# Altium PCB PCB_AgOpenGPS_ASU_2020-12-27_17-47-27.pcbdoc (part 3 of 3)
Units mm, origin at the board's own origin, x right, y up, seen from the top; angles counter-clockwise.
Board outline 200.19 x 135.91 mm, 2 copper layers (Top Layer, Bottom Layer); 260 components, 183 nets, 970 pads, 382 vias.
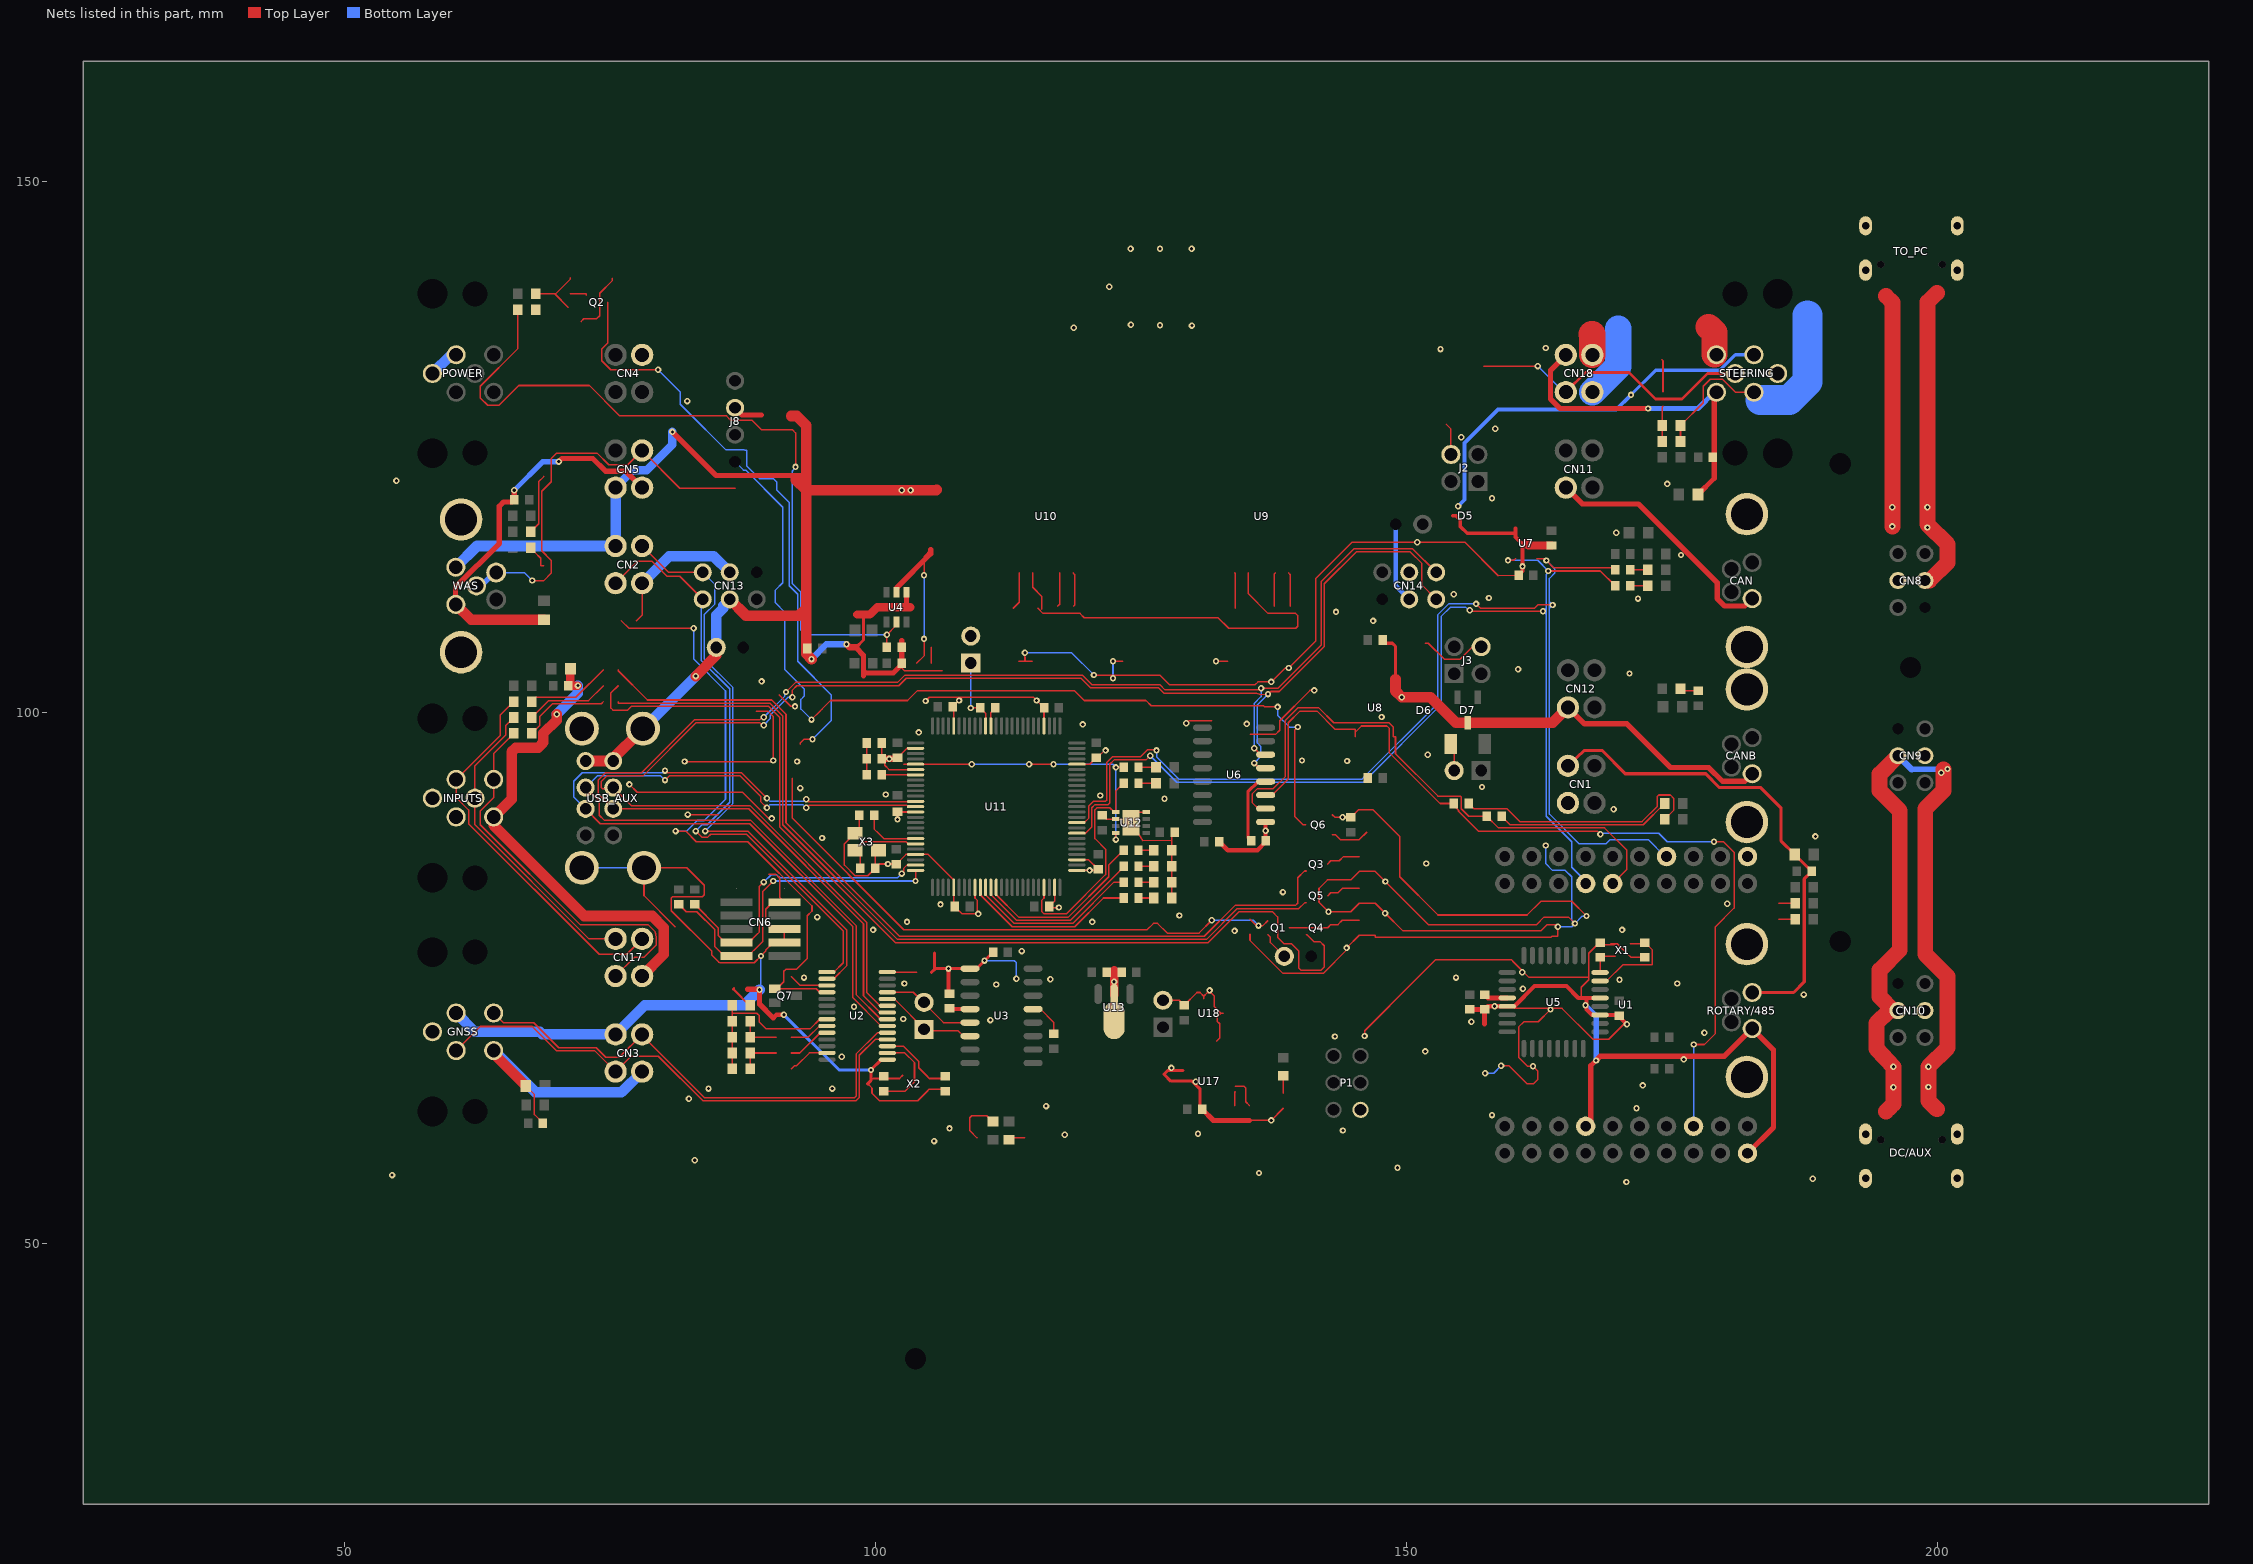
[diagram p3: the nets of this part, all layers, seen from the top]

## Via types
v1: diameter 0.6, hole 0.3, Top Layer to Bottom Layer, 381 vias
v2: diameter 0.61, hole 0.305, Top Layer to Bottom Layer, 1 vias

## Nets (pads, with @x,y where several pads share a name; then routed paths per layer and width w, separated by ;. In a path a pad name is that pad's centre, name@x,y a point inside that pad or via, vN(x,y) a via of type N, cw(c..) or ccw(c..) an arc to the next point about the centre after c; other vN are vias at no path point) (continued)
GND: 12V.1 BOOT.2 C1.1 C2.2 C3.2 C4.2 C5.1 C6.1 C8.1 C9.1 C10.1 C11.2 C12.1 C13.1 C14.2 C15.2 C17.1 C18.1 C19.1 C20.1 C21.1 C22.2 C23.2 C24.1 C25.1 C26.2 C27.1 C28.1 C29.1 C32.2 C33.1 C34.2 C35.2 C36.2 C37.1 C38.2 C39.1 C40.2 C41.1 C42.1 C43.1 C44.1 C45.1 C46.1 C47.1 C48.1 C49.1 C50.1 C51.1 C52.2 C53.2 C54.1 CAN.3 CAN.Shield CANB.3 CANB.Shield CN1.3 CN2.4 CN3.4 CN4.3 CN5.2 CN6.3 CN6.5 CN6.9 CN7.2 CN11.3 CN12.3 CN13.4 CN14.4 CN15.2 D2.2 D5.3 D6.3 D7.3 GNSS.4 GNSS.Shield INPUTS.3 INPUTS.Shield LED1.1 LED2.1 LED3.1 LED4.1 P1.6 POWER.3 POWER.Shield Q6.2 R1.1 R10.1 R14.1 R16.2 R18.1 R25.2 R26.2 R27.2 R36.1 R38.2 R42.2 R44.1 R47.1 R70.1 R77.2 R81.2 R82.2 R93.2 ROTARY/485.3 ROTARY/485.Shield STEERING.3 STEERING.Shield U1.1 U1.4 U1.27 U2.1 U3.1 U4.1 U5.3 U5.5 U5.21 U6.1 U7.2 U7.8 U7.9 U8.5 U11.2 U11.6 U11.14 U11.22 U11.30 U11.34 U11.49 U11.51 U11.53 U11.71 U11.79 U11.96 U12.2 U12.8 U12.9 U13.2 U17.1 U17.3 U18.5 U18.7 U18.10 U18.12 USB_AUX.4 USB_AUX.8 USB_AUX.9 WAS.3 WAS.Shield X1.2 X1.4 X2.2 X2.4 X3.2 X3.4 | length 896
  Top Layer w0.145: 72.289,136.798 72.541,137.05 73.737,137.05 74.037,137.35 74.037,139.45 75.237,140.65 75.237,140.85 ; v1(76.837,93.2) 77.587,92.45 87.487,92.45 89.937,90 v1@90.237,90 ; USB_AUX.9@78.211,85.349 78.211,82.727 81.137,79.8 ; USB_AUX.9@78.212,85.351 82.238,85.351 83.887,83.7 83.887,82.801 83.688,82.6 80.887,82.6 80.788,82.501 80.788,81.3 84.588,77.5 84.588,77.119 85.245,76.463 85.387,76.4 ; v1(82.037,95.35) 90.287,95.35 v1(90.387,95.45) ; v1(82.337,90.35) 85.187,90.35 ; 85.388,76.4 88.588,76.4 v1(89.228,77.04) 89.688,77.5 89.688,77.601 90.381,78.295 CN6.3@91.437,78.295 ; 88.786,100.101 89.889,100.101 90.386,99.6 v1@90.386,95.45 ; 89.987,84.75 90.587,84.75 90.987,84.35 90.987,82.555 CN6.9@91.437,82.105 90.343,82.105 89.688,81.449 89.688,80.101 90.221,79.565 CN6.5@91.437,79.565 ; CN6.5@90.252,79.565 CN6.5@91.437,79.565 CN6.3@91.437,78.295 ; 90.937,101.65 92.037,100.55 v1(92.437,100.55) ; C37.1@98.487,90.3 98.487,89 X3.2@98.087,88.6 97.087,87.6 97.087,85.6 98.088,84.599 99.287,84.599 C39.1@99.987,85.3 ; C12.1@99.287,65 99.688,64.599 99.688,64.101 100.386,63.4 103.988,63.4 X2.2@104.787,64.2 ; X3.4@100.287,87 99.987,86.7 C39.1@99.987,85.3 ; R82.2@100.587,95.6 100.887,95.6 100.887,95 101.288,94.599 U11.6@103.787,94.6 ; R82.2@100.587,95.6 R81.2@100.587,97.1 ; v1(102.087,89.9) C49.1@102.087,90.625 ; C49.1@102.087,90.7 102.187,90.6 U11.14@103.787,90.6 ; C47.1@102.087,95.7 102.987,96.6 U11.2@103.787,96.6 ; R70.1@102.487,104.6 102.487,104.15 102.737,103.9 106.287,103.9 ; v1(104.737,101.05) 105.087,101.4 108.48,101.4 ; U11.96@107.387,98.7 107.387,100.4 C46.1@107.287,100.5 108.187,101.4 114.887,101.4 C43.1@115.887,100.4 U11.79@115.887,98.7 ; U11.34@109.387,83.5 109.388,82.501 109.586,82.3 109.586,81.101 109.487,81 108.187,81 107.488,81.701 107.387,81.8 U11.30@107.387,83.5 107.387,84.2 104.987,86.6 U11.22@103.787,86.6 102.887,86.6 C51.1@101.987,85.7 100.387,85.7 C39.1@99.987,85.3 ; R26.2@113.487,104.8 R42.2@114.787,104.8 ; v1(114.087,105.6) 114.097,104.8 ; U11.49@116.887,83.5 116.887,82.2 C50.1@116.387,81.7 116.487,81.6 v1(117.287,81.6) ; U11.51@118.987,85.1 v1(120.185,85.1) 120.887,85.1 C41.1@120.987,85.2 120.087,86.1 U11.53@118.987,86.1 ; U11.71@118.987,95.1 120.187,95.1 C42.1@120.787,95.7 ; v1(120.587,103.5) 126.787,103.499 127.686,102.6 135.786,102.6 136.038,102.849 v1(137.287,102.85) 138.598,104.16 v1@138.946,104.16 ; C42.1@120.788,95.701 120.887,95.701 121.588,96.4 v1(121.687,96.4) ; C40.2@121.387,90.3 121.757,89.93 U12.2@122.655,89.93 123.757,89.93 v1(124.087,89.6) ; C53.2@121.787,75.5 C52.2@123.187,75.5 ; v1(122.387,104.8) R25.2@123.287,104.8 ; U12.8@125.52,90.591 124.087,90.591 v1(124.087,89.6) ; CN15.2@127.087,72.87 128.617,72.87 C15.2@129.087,72.4 ; LED1.1@127.937,82.5 127.937,88.45 C45.1@128.187,88.7 ; 127.937,87.94 125.187,87.9 v1(124.087,89.6) ; C15.2@129.087,72.4 130.287,73.6 130.587,73.6 130.939,73.248 U18.12@130.939,73.001 ; v1(129.287,98.95) 129.537,99.2 131.687,99.2 ; 130.939,73.138 130.939,73.252 131.287,73.6 131.587,73.6 131.939,73.248 U18.10@131.939,73.001 131.939,72.248 132.537,71.651 ; v1(132.087,104.8) R27.2@133.187,104.8 ; C8.1@132.137,69 132.439,69.303 132.439,70.301 132.439,70.648 132.187,70.9 132.187,71.301 132.537,71.651 ; U18.7@132.789,71.651 132.537,71.651 ; C25.1@135.239,61.551 v1(137.287,61.551) R10.1@138.429,62.692 ; R16.2@135.287,79.1 135.287,78.5 138.387,75.4 142.187,75.4 144.387,77.6 v1(144.387,77.8) R44.1@145.587,79 C28.1@147.087,79 ; 135.337,97.901 137.686,97.901 138.088,98.3 138.088,99.199 140.937,102.049 v1@141.336,102.049 ; v1(138.947,104.161) 141.486,106.7 141.486,112.6 144.887,116.001 v1(151.047,116.001) 155.527,116.001 158.672,112.854 C2.2@160.587,112.9 ; Q6.2@143.037,90.35 143.287,90.1 144.014,90.1 144.787,90.1 145.487,90.8 146.887,90.8 149.387,88.3 149.387,84.5 152.987,80.9 161.387,80.9 162.687,82.2 165.587,82.2 v1(166.987,80.8) ; v1(146.087,69.5) 146.087,70 150.887,74.8 152.787,76.7 153.987,76.7 159.887,76.7 160.187,76.4 161.532,75.055 167.188,75.055 ; 147.087,79.001 147.087,78.8 163.632,78.8 163.729,78.897 164.288,78.897 164.288,79.801 164.087,79.999 163.432,79.999 163.289,79.999 162.682,79.4 149.688,79.4 v1(148.019,81.069) C29.1@147.087,82 ; C27.1@147.087,85 v1(148.037,84.05) 152.088,79.999 162.286,79.999 162.987,80.7 165.287,80.7 v1(165.887,80.1) ; C29.1@147.087,82 R47.1@145.587,82 144.787,81.2 142.687,81.2 141.787,82.1 141.787,83.4 142.587,84.2 144.787,84.2 R36.1@145.587,85 C27.1@147.087,85 ; v1(158.937,66.7) 159.687,66.7 161.387,65 161.987,65 162.387,65.4 162.387,66.202 v1(161.938,66.651) 161.438,66.651 160.587,67.5 160.587,70.35 161.087,70.85 162.436,70.85 v1@163.587,72.001 ; U5.21@159.518,72.3 160.188,72.3 160.188,72.1 164.686,72.1 167.587,69.199 169.088,69.199 170.488,70.601 v1@170.788,70.601 ; C5.1@167.987,78.1 169.587,78.1 X1.4@169.687,78.2 ; C5.1@167.988,78.099 167.188,77.302 167.188,74.802 166.487,74.101 166.487,73.08 U5.5@168.255,73.08 ; 169.287,78.2 169.887,78.2 X1.2@171.087,77 171.187,76.9 C6.1@172.487,76.9
  Top Layer w0.15: C12.1@99.287,65 99.787,65.5 100.787,65.5 102.287,65.5 X2.4@102.587,65.8 ; X2.2@104.787,64.2 105.087,64.5 C23.2@106.387,64.5
  Top Layer w0.3: R18.1@98.187,106.1 98.887,106.8 98.887,109.201 ; 98.286,109.201 98.786,109.201 98.987,109.001 ; C12.1@99.287,65 99.587,65.3 v1(99.587,66.3) 100.56,67.273 U2.1@101.132,67.273 ; C10.1@105.587,77.3 105.587,75.8 R1.1@105.287,75.5 105.632,75.845 v1(106.897,75.845) U3.1@108.915,75.845 109.532,75.845 v1(110.287,76.6) C35.2@111.087,77.4 ; U17.3@128.988,65.251 129.836,65.251 130.587,64.5 C14.2@130.587,62.6 ; U17.1@128.988,66.251 127.538,66.251 C9.1@127.187,65.9 127.837,65.251 129.837,65.251 ; C36.2@147.788,106.801 148.088,106.499 148.687,106.499 148.992,106.194 148.992,103.121
  Top Layer w0.35: D5.3@154.387,118.5 154.686,118.5 155.088,118.099 155.088,117.5 155.741,116.847 160.297,116.847 ; U7.8@160.297,117.333 160.297,116.491 160.887,115.899 U7.9@161.287,115.9 ; C2.2@160.587,112.9 160.957,113.27 v1(160.957,113.731) U7.2@160.957,114.468 ; v1@160.957,113.93 160.957,115.57 U7.9@161.287,115.9
  Top Layer w0.4: 90.387,71.2 90.687,71.5 v1(91.387,71.5) ; v1(106.897,75.845) 106.897,73.59 C1.1@106.987,73.5 ; C4.2@132.387,87.8 133.188,86.999 135.987,86.999 136.759,87.771 v1@136.759,88.594 ; U6.1@136.759,89.655 v1(136.759,88.827) 136.759,87.928 C38.2@136.787,87.9 ; U5.21@159.518,72.294 160.181,72.294 162.087,74.2 165.087,74.2 166.207,73.08 166.988,73.08 ; U5.3@168.255,71.482 167.503,71.482 166.988,72.001 166.988,73.08 ; U5.5@168.255,73.08 166.988,73.08 ; U5.3@168.256,71.483 169.904,71.483 v1(170.787,70.6)
  Top Layer w0.45: C22.2@155.987,72 157.187,72 C3.2@157.287,71.9 ; C33.1@157.387,70.6 157.387,71.9 C3.2@157.287,71.9 ; U5.21@159.518,72.3 v1(158.324,72.296) 157.681,72.294 C3.2@157.287,71.9
  Top Layer w0.5: v1(80.887,126.4) 84.987,122.3 93.487,122.3 ; 87.987,73.9 89.038,73.9 v1(89.087,73.85) 89.087,72.5 90.387,71.2 ; R18.1@98.187,106.1 98.887,105.35 98.887,103.4 ; 98.888,104 98.888,103.9 99.086,103.7 101.687,103.7 102.487,104.5 102.487,106.75 102.487,106.7 ; U4.1@102.937,111.3 102.937,109.951 102.987,109.9 ; C14.2@130.787,62.6 131.837,61.551 C25.1@135.239,61.551 ; CN11.3@165.037,121.15 166.588,119.6 171.887,119.6 179.287,112.2 179.287,110.7 179.987,110 181.887,110 CAN.3@182.587,110.7 ; CN12.3@165.238,100.451 166.787,98.899 170.788,98.899 174.887,94.8 178.486,94.8 179.787,93.499 181.89,93.499 CANB.3@182.587,94.2 ; U1.27@166.907,61 167.387,61.48 167.387,66.7 168.287,67.6 179.987,67.6 ROTARY/485.3@182.587,70.2 184.587,68.2 184.587,60.9 U1.4@182.147,58.46
  Top Layer w0.6: v1(97.287,106.4) 97.587,106.1 R18.1@98.187,106.1 ; R82.2@100.587,95.6 v1(101.312,95.6) 101.987,95.6 C47.1@102.087,95.7
  Top Layer w0.8: 98.288,109.201 99.487,109.201 100.188,109.9 103.287,109.9 ; U13.2@122.487,73.352 v1(122.487,74.613) 122.487,75.7 ; U7.9@161.287,115.9 161.487,115.7 C48.1@163.687,115.7
  Top Layer w1: USB_AUX.4@72.712,95.4 75.061,95.4 USB_AUX.9@78.112,98.451 ; v1(83.087,103.4) 85.017,105.356 CN7.2@85.017,106.1 ; CN13.4@86.287,110.63 87.817,109.1 92.787,109.1 93.387,109.7 C18.1@93.487,109.7 ; C32.2@92.087,127.9 92.587,127.9 93.487,127 93.487,105.5 v1(93.987,105) ; 92.487,121.9 93.487,120.9 v1(102.487,120.9) v1(103.325,120.9) 105.722,120.9 D2.2@105.787,120.965 ; 148.992,103.121 148.992,101.995 v1(149.586,101.401) 152.286,101.401 154.686,99.001 155.786,99.001 163.787,99.001 CN12.3@165.238,100.451
  Bottom Layer w0.145: USB_AUX.9@72.361,85.349 USB_AUX.9@78.211,85.349 ; v1(89.087,73.85) 89.228,73.991 v1(89.228,77.04) ; v1(110.287,76.6) 113.087,76.6 113.287,76.4 v1(113.287,74.9) ; v1(114.087,105.6) 118.487,105.6 v1(120.587,103.5) ; v1(122.387,103.2) v1(122.387,104.8) ; v1(157.437,66) 158.237,66 v1(158.937,66.7) ; v1(163.137,87.45) 163.137,85.75 163.787,85.1 164.987,85.1 165.587,84.5 165.587,80.4 v1(165.887,80.1) ; v1(164.287,79.8) 165.587,79.8 v1(165.887,80.1) ; v1(166.987,80.8) 166.587,80.8 v1(165.887,80.1)
  Bottom Layer w0.3: v1(91.387,71.5) 96.587,66.3 v1(99.587,66.3) ; v1(171.172,129.885) 173.488,132.201 179.538,132.201 181.006,133.669 STEERING.3@182.555,133.669
  Bottom Layer w0.35: v1(154.887,119.4) 155.487,120 155.487,125.346 158.641,128.5 162.421,128.5 ; 159.187,128.5 158.787,128.5 169.787,128.5 v1(171.172,129.885)
  Bottom Layer w0.5: v1(166.887,72.4) 167.887,71.4 v1(167.887,67.2)
  Bottom Layer w0.6: v1(93.987,105) 95.387,106.4 v1(97.287,106.4)
  Bottom Layer w0.8: CN5.2@75.537,121.15 77.189,122.801 78.486,122.801 80.887,125.201 v1(80.887,126.4)
  Bottom Layer w1: POWER.Shield@58.287,131.9 60.055,133.668 POWER.3@60.519,133.668 ; WAS.3@60.487,113.65 62.487,115.65 CN2.4@75.537,115.651 CN5.2@75.537,121.15 ; GNSS.4@60.519,71.668 62.286,69.9 68.387,69.9 68.636,69.651 75.538,69.651 78.287,72.4 87.638,72.4 v1(89.087,73.85) ; USB_AUX.9@78.112,98.451 78.138,98.451 v1(83.087,103.4) ; CN7.2@85.017,106.1 85.017,109.13 85.687,109.8 85.687,110.03 CN13.4@86.287,110.63
  other v1: 170.737,55.75 188.287,56.05 54.487,56.4 136.137,56.6 149.187,57.1 82.987,57.8 105.537,59.6 117.837,60.2 130.387,60.3 144.037,60.6 106.987,60.8 158.087,62.05 171.687,62.7 116.087,62.9 82.437,63.6 84.287,64.55 95.937,64.55 172.287,64.85 130.187,65.2 127.887,66.5 176.137,67.3 96.837,67.55 151.787,68.05 143.287,69.45 178.087,69.8 156.137,70.85 110.837,71 102.637,71.1 163.587,72 97.987,72.25 187.437,73.4 131.487,73.8 160.987,73.95 111.387,74.35 102.737,74.45 175.537,74.45 170.087,74.8 116.487,74.85 93.287,75 154.687,75 160.937,75.5 113.787,77.5 133.837,79.4 99.787,79.5 170.337,79.5 102.987,80.25 120.437,80.25 94.537,80.7 128.637,80.85 109.687,81 142.687,81.2 106.137,81.9 180.237,81.95 138.387,83.05 101.187,85.7 151.887,85.75 94.987,88.15 188.537,88.3 90.237,90 144.014,90.1 169.537,90.85 127.237,91.85 121.187,92.15 100.987,92.25 92.937,92.85 157.137,92.95 92.637,95.35 144.437,95.4 140.187,95.45 152.037,96 104.087,98.1 119.537,98.85 134.987,98.9 147.687,99.55 107.887,101.1 115.187,101.1 141.337,102.05 89.287,102.9 171.037,103.65 160.537,104.05 146.887,108.6 143.387,109.45 171.837,110.7 157.787,110.75 154.487,111.1 175.887,114.8 169.787,116.9 158.087,120.15 174.587,121.5 54.887,121.8 155.187,125.9 158.387,126.7 82.287,129.3 153.237,134.2 163.137,134.3
GND1: CN8.4 TO_PC.1 TO_PC.2 TO_PC.3 TO_PC.4 TO_PC.A1 TO_PC.A12 TO_PC.B1 TO_PC.B12
GND2: CN9.4 CN10.4 DC/AUX.1 DC/AUX.2 DC/AUX.3 DC/AUX.4 DC/AUX.A1 DC/AUX.A12 DC/AUX.B1 DC/AUX.B12
GNSS+: CN3.1 F1.1 GNSS.2 R64.2 | length 25.2
  Top Layer w0.145: F1.1@67.087,64.8 67.887,64 67.887,62.1 R64.2@68.687,61.3
  Top Layer w1: GNSS.2@64.055,68.132 64.055,67.832 F1.1@67.087,64.8
  Bottom Layer w1: GNSS.2@64.055,68.132 67.987,64.2 76.087,64.2 CN3.1@78.037,66.15
IN0: CN17.4 INPUTS.5 STEER.2 | length 29.3
  Top Layer w0.145: STEER.2@65.936,99.501 65.187,98.749 65.187,97.85 62.286,94.949 62.286,91.901 62.286,89.4 73.036,78.65 CN17.4@75.537,78.65
IN1: CN17.2 INPUTS.1 WORK.2 | length 36.9
  Top Layer w0.145: WORK.2@65.936,98 64.054,96.118 64.054,93.669 64.054,91.968 62.787,90.7 62.787,89.4 72.187,79.999 78.588,79.999 79.287,79.301 79.363,78.815 79.363,78.076 78.187,76.9 77.288,76.9 CN17.2@75.537,75.15
IN2: CN17.3 INPUTS.4 REMOTE.2 | length 36.3
  Top Layer w0.145: REMOTE.2@65.936,101 64.687,99.75 64.687,97.837 60.519,93.669 60.519,91.968 61.687,90.799 61.687,89.501 73.988,77.2 76.587,77.2 CN17.3@78.037,78.65
IN+: CN17.1 F4.2 INPUTS.2 R73.2 | length 45.8
  Top Layer w0.8: F4.2@71.288,104.101 71.288,102.501 71.087,102.501 v1(71.987,102.5)
  Top Layer w1: v1@69.988,99.801 69.988,99.25 68.738,98.003 68.738,97.152 68.238,96.651 66.137,96.651 65.738,96.25 65.738,91.815 64.054,90.131 64.054,89.334 72.586,80.799 78.987,80.799 80.087,79.699 80.087,77.2 CN17.1@78.037,75.15
  Bottom Layer w1: v1(69.987,99.8) 71.987,101.8 v1(71.987,102.5)
INH: R61.2 U9.3 U10.3 | length 37.6
  Top Layer w0.145: 115.289,109.801 115.786,109.3 119.287,109.3 119.688,108.899 132.286,108.899 133.287,107.901 139.589,107.901 139.787,108.099 139.787,109.1 139.586,109.3 136.988,109.3 135.118,111.17 U9.3@135.117,113.116
  Top Layer w0.15: 114.816,113.115 114.816,111.769 115.687,110.9 115.687,109.7
J1_1: CN14.3 J1.1 | length 7.6
  Bottom Layer w0.45: J1.1@149.017,117.7 149.017,111.901 CN14.3@150.287,110.631
J2_4: J2.4 R60.2 | length 3
  Top Layer w0.145: R60.2@153.787,127.1 154.217,126.67 J2.4@154.217,124.27
J4_2: J4.2 R92.1 | length 2.6
  Top Layer w0.145: R92.1@154.187,97 154.517,96.67 J4.2@154.517,94.5
J8_3: J8.3 R15.2 | length 2.8
  Top Layer w0.5: J8.3@86.787,128.67 87.457,128 R15.2@89.287,128
J13_2: J13.2 Q1.2 | length 2.7
  Top Layer w0.145: Q1.2@136.971,79.04 137.211,78.8 137.211,78.307 J13.2@138.517,77
LED1_2: LED1.2 R84.1 | length 1.5
  Top Layer w0.145: R84.1@124.787,82.5 LED1.2@126.237,82.5
LED2_2: LED2.2 R85.1 | length 1.5
  Top Layer w0.145: R85.1@124.787,84 LED2.2@126.237,84
M_FB_0V: C24.2 U17.6 | length 1.3
  Top Layer w0.145: C24.2@133.839,62.951 133.839,64.2 U17.6@133.89,64.251
M_FB_12V: C25.2 U17.7 | length 2.9
  Top Layer w0.145: U17.7@133.89,64.751 134.737,64.751 134.887,64.6 134.887,63.303 C25.2@135.239,62.951
MA: CN18.4 M1.2 M2.1 STEERING.4 STEERING.@180.987,139.4 STEERING.@184.987,139.4 U10.8 | length 29.8
  Top Layer w0.145: M1.2@175.837,125.501 M2.1@175.837,127 177.986,129.151 177.986,130.7 178.636,131.35 179.787,131.35 181.006,130.131 STEERING.4@182.555,130.131
  Bottom Layer w2.5: CN18.4@167.536,130.149 169.987,132.6 169.987,136.1
  Bottom Layer w2.8: 183.337,129.4 186.086,129.4 187.806,131.119 187.806,137.378
  other v1: 129.812,136.411 126.815,136.437 124.072,136.487 122.04,140.069 124.046,143.65 126.815,143.65 129.787,143.65
  other v2: 118.687,136.2
MB: CN18.2 R24.2 STEERING.2 U9.4 U9.8 | length 7.9
  Top Layer w0.145: 174.087,133.2 174.187,133.1 R24.2@174.187,130.2
  Top Layer w2.45: 178.487,136.3 179.019,135.768 STEERING.2@179.019,133.668
  Top Layer w2.5: 167.488,135.6 167.536,135.6 CN18.2@167.536,133.649
OUT: J8.1 Q6.3 | length 88.4
  Top Layer w0.145: v1@93.988,99.301 94.788,100.09 94.986,100.299 95.789,101.101 103.033,101.101 103.932,102.001 118.786,102.001 119.685,101.101 125.487,101.101 125.987,100.601 136.388,100.601 ; 135.158,100.601 136.545,100.601 136.646,100.5 v1(137.887,100.5) ; v1(139.787,98.6) 139.487,98.3 139.487,90.2 140.287,89.4 Q6.3@140.538,89.4
  Bottom Layer w0.145: 86.998,123.591 J8.1@86.787,123.59 87.577,122.801 87.788,122.801 91.288,119.298 91.288,112.201 90.587,111.5 90.587,110.301 91.486,109.4 91.486,104 93.213,102.275 93.287,102.2 93.287,101.5 92.987,101.2 92.987,100.301 v1@93.988,99.301 ; v1(137.887,100.5) 137.887,99.72 139.007,98.6 v1(139.787,98.6)
  other v1: 93.987,99.3
Q3_2: Q3.2 R40.1 | length 85.2
  Top Layer w0.145: R40.1@75.787,104 75.786,103.9 78.537,101.15 90.237,101.15 91.587,99.8 91.588,89.598 102.286,78.899 130.988,78.899 133.886,81.8 139.586,81.8 139.787,82.001 139.787,84.401 140.427,85.041 140.572,85.041
Q4_3: Q1.3 Q4.3 R43.2 R44.2 | length 6.9
  Top Layer w0.145: Q1.3@139.003,79.7 Q4.3@142.603,79.7 142.903,80 143.587,80 143.987,80.4 R43.2@144.087,80.4 R44.2@145.587,80.4
Q5_3: Q5.3 R46.2 R47.2 | length 3.3
  Top Layer w0.145: Q5.3@142.603,82.7 142.903,83 143.587,83 143.987,83.4 R46.2@144.087,83.4 R47.2@145.587,83.4
R3_2: AUX0.1 GNSS_.2 R3.2 | length 4.8
  Top Layer w0.15: AUX0.1@88.237,66.408 GNSS_.2@88.237,67.9 ; R3.2@90.687,67.9 GNSS_.2@88.237,67.9 ; GNSS_.2@88.237,67.9 87.937,68.2 GNSS_.2@88.237,67.9
R4_1: ARDU.1 AUX1.2 R4.1 | length 4
  Top Layer w0.15: ARDU.1@88.237,70.9 AUX1.2@88.237,69.4 R4.1@90.687,69.4
R8_2: Q2.1 R8.2 | length 1.6
  Top Layer w0.145: R8.2@71.287,139.4 72.771,139.4 Q2.1@72.771,139.261
R10_2: LED.2 R10.2 | length 1.6
  Top Layer w0.145: R10.2@138.429,64.092 LED.2@138.43,65.743
R14_2: R14.2 USB:.1 | length 2.4
  Top Layer w0.2: R14.2@86.587,73.9 86.688,74 86.688,73.85 88.136,72.399 USB:.1@88.237,72.4
R15_1: 12V.2 C44.2 R15.1 U4.5 | length 73.7
  Top Layer w0.145: 12V.2@66.337,137.9 66.337,134.25 62.787,130.7 62.787,129.6 63.487,128.9 64.555,128.9 66.426,130.771 73.069,130.771 75.936,127.901 85.987,127.901 86.388,127.5 88.387,127.5 R15.1@89.287,126.6 ; R15.1@89.287,126.6 92.187,126.6 92.487,126.3 v1(92.487,123.1) ; C44.2@101.087,106.1 101.087,107.302 101.987,108.201 U4.5@101.987,108.5 ; C44.2@101.087,106.1 v1(101.087,107.3)
  Bottom Layer w0.145: v1(92.487,123.1) 92.187,122.699 92.187,112.1 92.987,111.299 92.987,107.7 93.389,107.299 v1(101.087,107.3)
R19_2: C16.2 R19.2 | length 1.5
  Top Layer w0.145: R19.2@105.287,104.6 C16.2@105.287,106.1
R22_1: R22.1 TXD.2 | length 4.7
  Top Layer w0.145: R22.1@109.587,59.9 108.887,60.6 108.887,61.8 109.087,62 110.487,62 111.037,61.45 TXD.2@111.087,61.45
R23_1: R23.1 RXD.2 | length 1.6
  Top Layer w0.145: RXD.2@112.587,59.75 112.737,59.9 R23.1@114.087,59.9
R24_1: M1.1 M2.2 R24.1 | length 3.3
  Top Layer w0.145: M1.1@174.137,125.5 174.137,128.75 R24.1@174.187,128.8
R31_2: CHB.1 R31.2 | length 1.5
  Top Layer w0.145: R31.2@185.087,80.5 CHB.1@186.637,80.5
R32_2: CHA.1 R32.2 | length 1.5
  Top Layer w0.145: 185.087,82 CHA.1@186.637,82
R33_1: Q6.1 R33.1 | length 3.7
  Top Layer w0.145: Q6.1@143.037,88.45 143.337,88.45 143.787,88 145.587,88 R33.1@146.287,88.7
R36_2: Q3.3 R36.2 R39.2 | length 3.3
  Top Layer w0.145: Q3.3@142.603,85.7 142.903,86 143.687,86 R39.2@144.087,86.4 R36.2@145.587,86.4
R40_2: R40.2 REMOTE.1 | length 8
  Top Layer w0.145: REMOTE.1@67.637,101 68.037,101.401 71.789,101.401 R40.2@74.387,104
R41_1: Q4.2 R41.1 | length 95.1
  Top Layer w0.145: 75.786,102.501 75.088,101.8 75.088,100.4 75.286,100.2 76.688,100.2 77.036,100.55 89.937,100.55 ; 90.087,100.4 89.937,100.55 ; 137.887,80.72 137.407,81.2 134.255,81.2 131.354,78.3 101.888,78.3 90.988,89.199 90.988,99.501 90.188,100.299 89.937,100.55 ; 137.887,80.7 137.887,78.8 138.486,78.201 139.187,78.201 139.888,77.5 139.888,75.899 140.087,75.699 141.986,75.699 142.286,76.001 142.286,78 141.887,78.399 141.288,78.399 140.648,79.039 Q4.2@140.571,79.04
R41_2: R41.2 STEER.1 | length 8
  Top Layer w0.145: STEER.1@67.638,99.501 69.238,101.099 72.987,101.099 74.387,102.501
R45_1: Q5.2 R45.1 | length 81.6
  Top Layer w0.145: R45.1@75.787,101 75.786,100.85 90.087,100.85 91.288,99.651 91.288,89.4 102.088,78.6 131.186,78.6 134.087,81.5 139.888,81.5 140.427,82.039 Q5.2@140.571,82.04
R45_2: R45.2 WORK.1 | length 8.5
  Top Layer w0.145: WORK.1@67.637,98 68.387,98.75 68.387,99.6 69.587,100.8 74.187,100.8 R45.2@74.387,101
R50_1: CN2.1 CN13.3 R50.1 | length 13.7
  Top Layer w0.145: R50.1@77.487,108.6 78.037,109.151 CN2.1@78.037,112.151
  Bottom Layer w1: CN2.1@78.037,112.151 80.587,114.7 84.757,114.7 CN13.3@86.287,113.17
R51_1: MOT.1 R8.1 R49.2 R51.1 | length 5.7
  Top Layer w0.145: R8.1@69.887,139.4 71.287,140.8 R51.1@71.287,140.9
  Top Layer w0.15: MOT.1@68.037,139.4 R8.1@69.887,139.4 ; 69.805,139.399 71.084,138.121
R57_2: R57.2 WAS2.1 | length 5.7
  Top Layer w0.145: WAS2.1@67.537,117 68.288,117.751 68.287,121.7 68.786,122.201
R58_2: R58.2 WAS1.1 | length 2.6
  Top Layer w0.145: WAS1.1@67.537,115.501 67.887,115.501 67.887,115.099 68.487,114.5 68.487,113.801 68.786,113.801
R59_2: CN18.3 R59.2 STEERING.5 | length 27.5
  Top Layer w0.145: R59.2@157.287,132.6 v1(162.387,132.6)
  Top Layer w0.28: CN18.3@165.037,130.15 166.886,132 170.988,132 173.488,129.501 175.987,129.501 178.387,131.901 STEERING.5@180.987,131.9
  Bottom Layer w0.145: v1(162.387,132.6) 164.839,130.149 CN18.3@165.037,130.15
R63_1: Q2.3 R63.1 | length 56.9
  Top Layer w0.145: Q2.3@74.803,138.6 74.803,134.767 74.237,134.2 74.237,133.1 75.088,132.249 v1(79.537,132.25) ; R63.1@92.937,97 92.937,97.101 93.287,97.449 v1(94.087,97.45)
  Bottom Layer w0.145: v1(79.537,132.25) 81.636,130.151 81.637,129 82.187,128.45 85.936,124.701 87.664,124.701 87.714,124.65 87.887,124.65 87.887,123.199 89.088,122 90.386,122 90.737,121.65 90.737,120.901 91.888,119.75 91.888,111.899 92.688,111.101 92.688,104.8 95.837,101.65 95.837,99.199 v1(94.087,97.45)
R65_2: J3.4 R65.2 | length 6.4
  Top Layer w0.145: R65.2@151.787,106.5 152.087,106.5 153.587,105 155.087,105 156.257,106.17 J3.4@157.057,106.17
R67_1: R67.1 TX485.1 | length 16.5
  Top Layer w0.145: R67.1@158.987,90.2 159.787,89.4 172.337,89.4 TX485.1@174.338,91.401
R69_1: R69.1 TXCAN.1 | length 1.6
  Top Layer w0.145: R69.1@171.087,111.9 TXCAN.1@172.737,111.9
R72_1: FCAN1.2 R72.1 | length 1.7
  Top Layer w0.145: FCAN1.2@175.837,102.2 176.037,102 R72.1@177.487,102
R80_2: R80.2 R81.1 R82.1 | length 3
  Top Layer w0.145: R80.2@99.187,94.1 R81.1@99.187,97.1
R86_1: LED3.2 R86.1 | length 1.5
  Top Layer w0.145: R86.1@124.787,85.5 LED3.2@126.237,85.5
R87_1: LED4.2 R87.1 | length 1.5
  Top Layer w0.145: R87.1@124.787,87 LED4.2@126.237,87
R88_1: R88.1 TXCAN1.1 | length 1.6
  Top Layer w0.145: R88.1@124.788,93.301 TXCAN1.1@126.437,93.301
R89_1: R89.1 RXCAN1.1 | length 1.6
  Top Layer w0.145: R89.1@124.787,94.8 RXCAN1.1@126.437,94.8
ROT+: CN1.1 F6.2 R75.2 ROTARY/485.1 | length 46.1
  Top Layer w0.3: CN1.1@165.237,94.95 166.787,96.4 168.438,96.4 170.638,94.2 178.207,94.2 179.507,92.9 183.388,92.9 185.288,91 185.288,87.901 F6.2@186.586,86.601 ; ROTARY/485.1@182.588,73.601 186.487,73.601 187.488,74.602 187.488,84.299 R75.2@188.187,85 ; F6.2@186.587,86.6 R75.2@188.187,85
RX485_1: R66.1 RX485.1 | length 24.1
  Top Layer w0.145: R66.1@155.888,91.401 156.388,90.901 159.487,90.901 160.689,89.699 172.218,89.699 173.663,91.145 173.663,92.077 173.787,92.201 174.887,92.201 175.187,91.899 175.187,90.751 RX485.1@174.337,89.9
RXCAN_1: R68.1 RXCAN.1 | length 1.6
  Top Layer w0.145: R68.1@171.087,113.4 RXCAN.1@172.737,113.4
RXD485: R66.2 U1.11 U6.3 U8.1 | length 86.9
  Top Layer w0.145: U6.3@136.759,92.196 137.381,92.196 138.888,93.7 138.888,99.001 139.988,100.101 141.588,100.101 143.287,98.401 145.182,98.401 145.182,97.886 ; U8.1@145.182,97.68 145.182,98.094 145.786,98.701 148.187,98.701 148.387,98.5 148.387,96.199 153.188,91.401 154.486,91.401 154.486,91.2 154.925,90.761 154.925,90.662 156.787,88.8 167.988,88.8 v1(168.287,88.5) ; v1@177.087,68.701 178.088,68.701 179.088,69.702 179.088,79.75 180.887,81.548 180.887,86.801 179.888,87.799 v1(178.987,87.8)
  Bottom Layer w0.145: v1(168.287,88.5) 168.387,88.599 173.787,88.599 174.587,87.799 v1(178.987,87.8) ; U1.11@177.067,61 177.087,61.02 v1(177.087,68.7)
RXDCAN: R68.2 U1.13 U7.4 U11.60 | length 110.4
  Top Layer w0.145: U11.60@118.987,89.6 119.688,89.6 120.087,89.999 120.087,91.15 120.536,91.599 121.687,91.599 121.788,91.701 121.788,95.249 122.337,95.8 124.986,95.8 125.639,96.453 126.434,96.453 v1(126.487,96.4) ; v1(156.587,110.2) 156.989,109.798 156.991,109.8 162.087,109.8 162.387,110.1 v1@163.787,110.1 ; U7.4@162.278,114.468 163.02,114.467 163.886,113.601 169.487,113.601 R68.2@169.687,113.4
  Bottom Layer w0.145: v1(126.487,96.4) 126.487,95.8 128.588,93.7 145.847,93.7 152.987,100.84 152.987,109.199 153.988,110.2 v1(156.587,110.2) ; v1(163.204,114.284) 163.988,113.499 163.988,113.1 163.488,112.6 163.488,90.4 166.287,87.601 168.824,87.601 169.223,88 172.789,88 174.387,86.4 U1.13@174.526,86.4 ; 163.488,109.733 163.488,109.8 v1(163.787,110.1) 163.488,110.4 163.488,110.644
RXDCAN1: R89.2 U11.5 U12.4 | length 28.2
  Top Layer w0.145: 102.687,95.1 U11.5@103.787,95.1 108.487,95.1 v1(109.087,95.1) ; v1(114.487,95.1) v1(116.787,95.1) ; v1(122.655,88) U12.4@122.655,88.61 ; v1(122.655,94.8) R89.2@123.387,94.8
  Bottom Layer w0.145: v1(109.087,95.1) v1(114.487,95.1) ; v1(116.787,95.1) 122.355,95.1 v1(122.655,94.8) v1(122.655,88)
S$68: 
S$18375: 
SERVO+: CN18.1 F7.2 R76.1 STEERING.1 | length 31.5
  Top Layer w0.5: CN18.1@165.037,133.65 163.587,132.2 163.587,129.9 163.587,129.5 164.387,128.7 164.487,128.6 168.187,128.6 v1(172.787,128.6) ; F7.2@177.487,120.5 179.019,122.032 STEERING.1@179.019,130.132
  Bottom Layer w0.5: v1(172.787,128.6) 177.487,128.6 STEERING.1@179.019,130.132
STEERENABLE: Q1.1 R16.1 R63.2 | length 55.5
  Top Layer w0.145: 92.187,93.799 92.187,90.002 102.688,79.501 125.588,79.501 126.188,80.101 126.586,80.101 127.488,79.199 130.488,79.199 v1(131.687,80.4) ; R16.1@135.287,80.5 135.887,79.9 v1(136.087,79.9) ; v1@136.053,79.9 136.511,79.9 Q1.1@136.971,80.36
  Bottom Layer w0.145: v1(131.687,80.4) 135.587,80.4 v1(136.087,79.9)
SW!: L7.1 R19.1 U4.2 | length 16.6
  Top Layer w0.145: R19.1@103.887,104.6 104.587,105.3 104.587,106.3 v1(104.587,106.9) ; v1(104.587,112.9) 104.587,114.675 L7.1@105.212,115.3
  Top Layer w0.5: U4.2@101.987,111.3 101.987,111.699 105.212,114.925 L7.1@105.212,115.3
  Bottom Layer w0.145: v1(104.587,106.9) v1(104.587,112.9)
SWCLK: CN6.4 R78.2 U11.24 | length 28.7
  Top Layer w0.145: R78.2@82.987,81.9 85.187,79.7 85.187,79 85.892,78.295 CN6.4@86.937,78.295 88.082,78.295 88.887,79.1 89.087,79.3 89.087,80.8 89.087,83.6 v1(89.487,84) ; v1(102.487,84.8) 102.66,84.973 102.66,85.272 102.987,85.6 U11.24@103.787,85.6
  Bottom Layer w0.145: v1(89.487,84) 90.187,84.7 90.687,84.7 90.987,84.4 91.787,84.4 102.087,84.4 v1(102.487,84.8)
SWDIO: CN6.2 R79.2 U11.25 | length 31.9
  Top Layer w0.145: R79.2@81.487,81.9 82.187,81.2 83.187,81.2 84.887,79.5 84.887,77.9 85.762,77.025 CN6.2@86.937,77.025 88.012,77.025 88.987,78 89.387,78.4 89.387,81.3 89.387,83.1 v1@90.387,84.1 ; v1@103.787,84.101 U11.25@103.787,85.1
  Bottom Layer w0.145: v1@90.387,84.1 v1(103.787,84.1)
  other v1: 90.387,84.1
TXD485: R67.2 U1.22 U6.2 U8.4 | length 55.4
  Top Layer w0.145: U6.2@136.759,90.926 136.063,90.926 135.487,91.5 135.487,92.3 135.987,92.801 137.488,92.801 138.588,93.9 138.588,99.199 139.787,100.4 141.786,100.4 143.185,99.001 148.385,99.001 148.786,98.599 148.786,97.68 U8.4@148.992,97.68 148.992,96.095 152.987,92.1 155.087,92.1 155.187,92 155.187,90.9 155.887,90.2 R67.2@157.587,90.2 ; R67.2@157.587,90.2 158.687,89.1 168.687,89.1 170.788,86.999 170.788,85.201 U1.22@169.446,83.86
TXDCAN: R69.2 U1.26 U7.1 U11.58 | length 107.2
  Top Layer w0.145: U11.58@118.987,88.6 119.787,88.599 120.386,89.199 120.386,91 ; 120.384,90.997 120.686,91.3 121.938,91.3 122.088,91.449 122.088,95.099 122.487,95.501 125.487,95.501 v1(125.887,95.9) ; v1(155.987,109.6) 156.086,109.6 156.188,109.501 v1@162.888,109.501 ; v1(159.587,114.3) 160.129,114.3 U7.1@160.297,114.468 ; v1(163.387,113.3) 168.287,113.3 R69.2@169.687,111.9
  Bottom Layer w0.145: v1(125.887,95.9) 128.387,93.4 145.967,93.4 153.287,100.72 153.287,109.001 154.186,109.9 155.587,109.9 v1(155.987,109.6) ; v1(159.587,114.3) 162.387,114.3 v1(163.387,113.3) 163.187,112.95 163.188,90.2 165.588,87.799 165.588,85.402 166.906,84.078 U1.26@166.906,83.86 ; 163.188,109.11 163.188,109.199 v1(162.887,109.5) ; 163.188,109.481 v1@162.888,109.501 ; 163.188,109.906 163.188,109.801 v1(162.887,109.5)
TXDCAN1: R88.2 U11.47 U12.1 | length 21.7
  Top Layer w0.145: U11.47@115.887,83.5 115.888,82.501 115.687,82.3 115.687,81.2 115.888,81 117.986,81 121.687,84.701 121.687,87.101 120.686,88.099 120.686,90.799 120.887,91 122.088,91 122.497,90.591 U12.1@122.655,90.591 122.655,92.568 R88.2@123.387,93.3
U2_2: C13.2 U2.2 X2.1 | length 8
  Top Layer w0.15: C13.2@100.787,64.3 102.787,64.299 103.687,65.2 103.687,67.001 102.78,67.908 U2.2@101.132,67.908
U2_3: C23.1 U2.3 X2.3 | length 6.9
  Top Layer w0.15: U2.3@101.132,68.543 102.645,68.543 104.087,67.1 104.087,66.5 X2.3@104.787,65.8 105.087,65.5 C23.1@106.387,65.5
U2_14: R1.2 U2.14 | length 2.8
  Top Layer w0.145: U2.14@101.132,75.528 101.16,75.5 R1.2@103.887,75.5
U2_17: R34.1 U2.17 | length 3.8
  Top Layer w0.145: R34.1@92.087,75.1 92.887,74.3 93.002,74.3
  Top Layer w0.15: 92.929,74.3 U2.17@95.444,74.3
U2_18: Q7.1 R50.2 U2.18 | length 61.2
  Top Layer w0.145: R50.2@76.087,108.6 76.787,107.9 v1(82.887,107.9) ; Q7.1@90.521,73.961 94.428,73.961 94.765,73.624 U2.18@95.444,73.624
  Top Layer w0.15: v1(81.187,88.8) 82.136,88.8 83.137,87.799 87.989,87.799 94.036,81.752 94.036,81.267 93.587,80.817 93.587,76.801 92.586,75.8 91.588,75.8 91.387,75.6 91.387,74.599 90.749,73.961 Q7.1@90.521,73.961
  Bottom Layer w0.15: v1(81.187,88.8) 82.238,88.8 83.236,89.801 83.887,89.801 85.888,91.8 85.888,102.001 82.888,105 v1@82.888,107.901
U2_22: ARDU.2 AUX0.2 AUX1.1 GNSS_.1 U2.22 USB:.2 | length 17.8
  Top Layer w0.15: AUX0.2@86.537,66.4 86.838,66.701 86.537,66.408 AUX0.2@86.537,66.4 USB:.2@86.537,72.4 ; ARDU.2@86.538,70.901 86.538,71.65 88.837,71.65 89.086,71.401 89.086,70.802 89.688,70.2 93.887,70.2 94.77,71.084 U2.22@95.444,71.084
U2_23: R4.2 U2.23 | length 3.8
  Top Layer w0.15: R4.2@92.087,69.4 93.686,69.4 94.735,70.449 U2.23@95.444,70.449
U2_24: R3.1 U2.24 | length 4.1
  Top Layer w0.15: 92.088,67.901 92.888,67.901 94.801,69.814 U2.24@95.444,69.814
U2_27: R2.1 U2.27 | length 4
  Top Layer w0.15: R2.1@92.087,66.4 92.388,66.7 92.586,66.7 93.795,67.909 U2.27@95.444,67.909
U3_4: C1.2 U3.4 | length 2
  Top Layer w0.4: C1.2@106.987,72.1 107.052,72.035 U3.4@108.915,72.035
U3_13: C7.2 U3.13 | length 3.5
  Top Layer w0.145: U3.13@114.859,72.035 115.552,72.035 116.787,70.8 C7.2@116.787,69.7
U5_7: C6.2 U5.7 X1.3 | length 9.4
  Top Layer w0.145: U5.7@168.255,74.68 168.867,74.68 170.386,76.199 173.188,76.199 173.188,77.601 C6.2@172.487,78.3 172.388,78.201 171.087,78.201
U5_8: C5.2 U5.8 X1.1 | length 3.5
  Top Layer w0.145: U5.8@168.256,75.481 168.256,76.831 167.987,77.1 168.087,77 X1.1@169.687,77
U5_20: C3.1 U5.20 | length 2.3
  Top Layer w0.45: C3.1@157.387,73.4 157.697,73.09 U5.20@159.518,73.09
U6_4: C38.1 U6.4 | length 6.8
  Top Layer w0.3: C38.1@135.387,87.9 135.087,88.2 135.087,92.5 136.052,93.465 U6.4@136.759,93.465
U9_2: R55.2 U9.2 | length 3.3
  Top Layer w0.15: U9.2@133.847,113.116 133.887,113.076 133.887,109.8
U9_5: R11.2 U9.5 | length 3.1
  Top Layer w0.145: R11.2@137.587,110 137.587,113.046 U9.5@137.657,113.116
U9_6: R12.2 U9.6 | length 3.2
  Top Layer w0.145: U9.6@138.927,113.116 139.087,112.956 R12.2@139.087,110
U10_2: R62.1 U10.2 | length 3.5
  Top Layer w0.15: R62.1@112.987,109.8 113.547,110.36 U10.2@113.547,113.116
U10_5: R21.1 U10.5 | length 3.2
  Top Layer w0.15: R21.1@117.187,110 117.357,110.17 U10.5@117.357,113.116
U10_6: R20.1 U10.6 | length 3.2
  Top Layer w0.15: U10.6@118.627,113.116 118.787,112.956 118.787,110.1 R20.1@118.687,110
U11_7: R80.1 U11.7 | length 3.2
  Top Layer w0.145: R80.1@100.587,94.1 U11.7@103.787,94.1
U11_19: C37.2 U11.19 X3.1 | length 5.6
  Top Layer w0.145: C37.2@99.887,90.3 99.887,89 X3.1@100.287,88.6 100.787,88.1 U11.19@103.787,88.1
U11_20: C39.2 U11.20 X3.3 | length 8
  Top Layer w0.145: C39.2@98.587,85.3 98.587,86.5 X3.3@98.087,87 98.887,87.8 102.887,87.8 103.087,87.6 U11.20@103.787,87.6
U11_35: R84.2 U11.35 | length 16.6
  Top Layer w0.145: U11.35@109.887,83.5 109.887,82.8 112.887,79.8 118.787,79.8 121.487,82.5 R84.2@123.387,82.5
U11_36: R85.2 U11.36 | length 16.4
  Top Layer w0.145: U11.36@110.387,83.5 110.387,82.8 113.087,80.1 118.587,80.1 122.487,84 R85.2@123.387,84
U11_37: R86.2 U11.37 | length 16.4
  Top Layer w0.145: U11.37@110.887,83.5 110.887,82.801 113.287,80.4 118.387,80.4 123.386,85.399 R86.2@123.386,85.501
U11_38: R87.2 U11.38 | length 16.8
  Top Layer w0.145: U11.38@111.387,83.5 111.387,82.801 113.488,80.7 118.187,80.7 121.987,84.5 121.987,85.6 R87.2@123.386,86.999
U11_89: R83.2 U11.89 | length 1.9
  Top Layer w0.145: U11.89@110.887,98.7 110.887,100 R83.2@111.287,100.4
U11_90: BOOT.1 R83.1 U11.90 | length 7
  Top Layer w0.145: v1(108.987,100.4) R83.1@109.887,100.4 110.387,99.9 U11.90@110.387,98.7
  Bottom Layer w0.145: v1(108.987,100.4) BOOT.1@108.987,104.63
USB_AUX0_N: CN14.6 U2.8 U6.6 USB_AUX.6 | length 142.6
  Top Layer w0.145: v1(89.487,99.528) 89.087,99.3 82.985,99.301 77.984,94.299 74.588,94.299 73.887,93.601 73.887,92.326 75.311,90.898 88.07,90.898 98.888,80.08 98.888,73.301 100.47,71.719 U2.8@101.133,71.719 ; v1(91.587,101.9) 92.49,102.801 102.088,102.801 102.787,103.499 119.487,103.499 120.386,102.603 126.787,102.603 127.288,102.1 135.888,102.1 136.188,102.1 v1(136.337,102.25) ; v1@135.687,96.6 136.282,96.005 U6.6@136.759,96.005 U6.6@137.392,96.005 ; v1(136.337,102.25) 137.917,102.25 141.989,106.322 141.989,112.302 145.087,115.4 150.597,115.4 CN14.6@152.827,113.17
  Bottom Layer w0.145: v1(89.487,99.528) 91.487,101.528 91.487,101.8 v1(91.587,101.9) ; v1@135.687,96.6 135.687,100.819 136.337,101.469 v1(136.337,102.25)
  other v1: 135.687,96.6
USB_AUX0_P: CN14.5 U2.9 U6.5 USB_AUX.7 | length 144.6
  Top Layer w0.145: USB_AUX.7@75.311,92.9 77.013,91.2 88.187,91.2 99.187,80.2 99.187,73.601 100.436,72.353 U2.9@101.132,72.353 ; USB_AUX.7@75.311,92.902 75.212,92.801 74.288,92.801 74.186,92.907 74.186,93.481 74.707,94 76.187,94 76.695,94 76.698,94.003 78.107,94.003 ; 78.108,94.002 83.104,99.001 89.087,99 v1(89.487,98.778) ; v1@92.187,101.401 92.187,102.079 92.609,102.501 102.213,102.501 102.911,103.199 119.365,103.199 120.267,102.3 126.668,102.3 127.168,101.8 135.888,101.8 136.338,101.65 136.988,101.701 137.237,101.95 138.037,101.95 138.204,102.117 ; v1(135.687,95.2) 136.152,94.735 U6.5@136.759,94.735 ; 138.187,102.1 142.286,106.199 142.286,112.1 145.288,115.099 150.386,115.099 151.486,113.999 151.486,111.97 CN14.5@152.827,110.631
  Bottom Layer w0.145: v1(89.487,98.778) 90.087,99.377 90.087,99.708 91.779,101.4 v1(92.187,101.4) ; v1(135.687,95.2) 136.287,95.8 136.287,96.8 135.987,97.1 135.987,100.7 v1(136.987,101.7)
USB_AUX1_N: U2.6 U11.12 USB_AUX.2 | length 77.9
  Top Layer w0.145: USB_AUX.2@72.712,90.899 74.087,89.501 88.166,89.501 97.887,79.781 97.887,73.1 100.539,70.449 U2.6@101.133,70.449 ; v1(80.187,94.5) 80.387,94.3 87.387,94.3 v1(89.787,91.9) ; v1(93.487,91.8) 93.736,91.551 103.137,91.551 103.188,91.599 U11.12@103.787,91.6 U11.12@103.787,91.65
  Bottom Layer w0.145: USB_AUX.2@72.712,90.899 71.588,92.023 71.588,93.499 72.385,94.299 79.986,94.299 v1(80.187,94.5) ; v1(89.787,91.9) 90.087,91.6 93.287,91.6 v1(93.487,91.8)
USB_AUX1_P: U2.7 U11.13 USB_AUX.3 | length 75.8
  Top Layer w0.145: USB_AUX.3@72.712,92.901 73.988,91.625 73.988,90.301 74.486,89.801 88.286,89.801 98.187,79.9 98.187,73.4 100.504,71.083 U2.7@101.132,71.083 ; v1(80.187,93.6) 80.587,94 85.987,94 87.267,94 89.187,92.08 89.187,91.6 v1(89.787,91) ; v1(93.487,91) 93.741,91.254 102.934,91.254 103.086,91.099 U11.13@103.787,91.1
  Bottom Layer w0.145: USB_AUX.3@72.712,92.901 73.811,94 79.787,94 v1(80.187,93.6) ; v1(89.787,91) 90.087,91.3 93.187,91.3 v1(93.487,91)
USB_NANO_N: U2.10 U3.6 UARDU.1 | length 9.2
  Top Layer w0.145: U2.10@101.132,72.988 101.811,72.976 104.803,69.984 107.806,69.984 108.294,69.495 U3.6@108.915,69.495
USB_NANO_P: U2.11 U3.5 UARDU.2 | length 9
  Top Layer w0.145: U2.11@101.132,73.623 103.564,73.623 106.422,70.765 U3.5@108.915,70.765
USB_RTU_N: CN3.2 GNSS.3 U2.4 | length 50.4
  Top Layer w0.145: CN3.2@75.538,66.151 76.988,67.601 79.564,67.601 83.767,63.4 98.187,63.4 98.487,63.7 98.487,67.68 99.984,69.178 U2.4@101.132,69.178
  Top Layer w0.15: GNSS.3@60.519,68.132 62.787,70.4 67.686,70.4 69.988,68.099 73.587,68.099 CN3.2@75.538,66.151
USB_RTU_P: CN3.3 GNSS.1 U2.5 | length 47.1
  Top Layer w0.145: CN3.3@78.037,69.651 78.037,69.549 83.889,63.7 98.067,63.7 98.189,63.824 98.189,67.802 100.2,69.813 U2.5@101.132,69.813
  Top Layer w0.15: GNSS.1@64.054,71.668 64.971,70.751 67.836,70.751 70.186,68.401 73.714,68.401 74.616,67.5 75.886,67.5 CN3.3@78.037,69.651
USB_UP_N: CN2.2 CN13.6 U2.15 | length 58.1
  Top Layer w0.145: CN2.2@75.537,112.15 77.587,114.2 78.987,114.2 80.386,112.801 81.578,112.801 CN13.6@83.747,110.631 ; v1(83.087,88.8) 83.688,88.201 84.189,88.201 84.489,88.5 87.867,88.5 96.988,79.379 96.988,76.4 96.117,75.529 U2.15@95.444,75.529
  Bottom Layer w0.145: v1(83.087,88.8) 83.686,89.4 84.166,89.4 86.287,91.52 86.287,102.201 83.587,104.901 83.587,110.471 CN13.6@83.747,110.631
USB_UP_P: CN2.3 CN13.5 U2.16 | length 57.1
  Top Layer w0.145: CN2.3@78.037,115.65 80.517,113.17 CN13.5@83.747,113.17 ; v1(83.987,88.8) 87.986,88.8 97.288,79.499 97.288,76.103 96.078,74.893 U2.16@95.442,74.893
  Bottom Layer w0.145: CN13.5@83.747,113.171 84.887,112.031 84.887,110.2 83.887,109.199 83.887,105.021 86.587,102.321 86.587,91.401 v1(83.987,88.8)
VBUS1: CN8.3 TO_PC.A4 TO_PC.A9 TO_PC.B4 TO_PC.B9 | length 51.4
  Top Layer w1.5: 195.187,139.2 195.787,138.6 195.786,119.3 v1(195.786,117.5) ; CN8.3@198.857,112.4 199.286,112.399 200.988,114.101 200.988,115.8 199.088,117.7 199.088,119.3 199.088,138.627 199.987,139.5
  other v1: 199.087,117.4 195.786,119.3 199.088,119.3
VBUS2: CN9.3 CN10.3 DC/AUX.A4 DC/AUX.A9 DC/AUX.B4 DC/AUX.B9 | length 78.9
  Top Layer w1.5: 195.187,62.4 195.487,62.7 195.887,63.1 v1(195.887,64.669) v1(195.887,66.6) 194.288,68.3 194.288,70.7 195.487,71.899 CN10.3@196.317,71.9 195.888,71.899 194.587,73.2 194.587,75.7 196.487,77.6 196.487,90.7 194.587,92.6 194.587,94.17 CN9.3@196.317,95.9 ; 199.987,62.6 199.187,63.4 v1(199.187,64.7) v1(199.187,66.598) 200.988,68.399 200.987,75.1 ; 200.587,94.6 200.587,92.6 198.888,90.901 198.888,77.2 200.988,75.099
  Bottom Layer w0.6: CN9.3@196.317,95.9 197.617,94.6 v1(200.987,94.65)
  other v1: 200.387,94.3
WAS: CN5.3 OP1.1 R28.1 R58.1 WAS.4 | length 39.7
  Top Layer w0.145: v1(67.687,112.4) 68.787,112.4 ; 68.786,112.399 69.487,113.1 69.487,114.299 68.588,115.201 68.588,120.799 69.487,121.701 69.487,123.9 69.988,124.401 73.787,124.401 74.887,123.301 76.688,123.301 CN5.3@78.037,124.65 ; CN5.3@78.037,124.65 81.587,121.1 R28.1@86.787,121.1
  Bottom Layer w0.145: OP1.1@64.287,113.15 66.937,113.15 v1(67.687,112.4)
  Bottom Layer w0.5: WAS.4@62.436,111.901 62.888,111.901 63.422,112.435 64.138,113.151 OP1.1@64.288,113.151
WAS+: CN5.1 F5.2 R74.2 WAS.1 | length 36.8
  Top Layer w0.5: WAS.1@60.487,110.15 60.463,111.777 64.588,115.899 64.588,119.4 64.986,119.801 65.786,119.801 R74.2@65.987,120 ; R74.2@65.987,120 v1(65.987,120.9) ; v1(70.187,123.6) 70.487,123.9 71.487,123.9 73.387,123.9 74.587,122.7 76.487,122.7 CN5.1@78.037,121.15
  Top Layer w1: WAS.1@60.487,110.15 61.937,108.7 F5.2@68.787,108.7
  Bottom Layer w0.5: v1(65.987,120.9) 68.687,123.6 v1(70.187,123.6)
pads on no net: CN6.6 CN6.7 CN6.8 CN6.11 CN6.12 DC/AUX. DC/AUX.A8 DC/AUX.B8 GNSS. INPUTS. POWER. Q7.2 STEERING.@180.987,124.4 STEERING.@184.987,124.4 TO_PC. TO_PC.A8 TO_PC.B8 U1.2 U1.3 U1.5 U1.6 U1.7 U1.9 U1.20 U1.25 U1.29 U1.33 U1.34 U1.35 U1.36 U1.37 U1.38 U1.39 U1.40 U2.25 U3.7 U3.8 U3.9 U3.10 U3.11 U3.12 U3.14 U3.15 U5.14 U5.19 U6.7 U6.8 U6.9 U6.10 U6.11 U6.12 U6.13 U6.14 U10.4 U11.3 U11.4 U11.8 U11.15 U11.16 U11.17 U11.18 U11.23 U11.26 U11.27 U11.28 U11.29 U11.39 U11.40 U11.41 U11.42 U11.43 U11.44 U11.46 U11.52 U11.55 U11.56 U11.57 U11.59 U11.61 U11.62 U11.63 U11.64 U11.65 U11.66 U11.67 U11.68 U11.69 U11.70 U11.72 U11.73 U11.74 U11.77 U11.78 U11.80 U11.81 U11.82 U11.83 U11.84 U11.85 U11.86 U11.87 U11.88 U11.91 U11.92 U11.93 U11.94 U11.95 U11.97 U11.98 U11.100 U17.2 U18.3 U18.8 U18.9 U18.11 U18.13 U18.15 U18.16

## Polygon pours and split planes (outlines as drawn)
+MOTOR on Bottom Layer (solid): 54.837,140.2 56.687,142.05 67.537,142.05 66.387,140.9 66.387,135.85 65.987,136.25 55.787,136.25 55.787,136.45
GND on Bottom Layer (solid): 53.637,125.5 63.737,125.55 64.137,125.95 64.687,127.2 65.387,128 72.187,135.8 100.187,135.8 112.487,123.5 112.487,115.75 117.537,110.7 140.337,110.7 140.337,133.3 143.687,136.65 182.387,136.65 189.137,129.9 189.137,56.05 188.537,55.45 54.637,55.45 53.787,56.3
GND2 on Bottom Layer (solid): 192.787,55.7 202.487,55.7 202.487,101.1 201.087,102.5 194.187,102.5 192.787,101.1 192.887,101
GND1 on Bottom Layer (solid): 192.687,146.2 201.787,146.2 202.487,145.5 202.487,107.4 201.087,106 194.287,106 192.787,107.5
GND1 on Top Layer (solid): 192.687,146.2 202.487,146.2 202.487,107.4 201.087,106 194.287,106 192.787,107.5
GND2 on Top Layer (solid): 192.987,55.7 202.387,55.7 202.487,55.8 202.487,101.1 201.087,102.5 194.187,102.5 192.887,101.2
+3V3 on Top Layer (solid): 104.187,88.7 104.187,97.2 105.387,98.4 105.287,98.4 105.387,98.4 117.387,98.4 118.687,97.1 118.687,85.1 117.387,83.8 107.987,84 105.137,86.85 104.487,87 104.187,88.2
GND on Top Layer (solid): 53.888,145.45 54.838,146.4 56.088,146.4 108.638,146.4 118.837,146.4 143.887,146.4 169.037,146.4 179.687,146.4 189.137,146.4 189.137,55.95 188.587,55.4 54.688,55.4 53.788,56.3

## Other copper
Top Layer:
  region: 103.287,38.6 103.287,39.6 104.287,39.6 104.287,38.6
  region: 191.387,78.9 191.387,77.9 190.387,77.9 190.387,78.9
  region: 196.987,104.7 197.987,104.7 197.987,103.7 196.987,103.7
  region: 191.387,123.9 191.387,122.9 190.387,122.9 190.387,123.9
  rectangle net +5V: 94.987,103.3 98.487,104.5
  rectangle net +5V: 95.287,104.1 97.487,104.9
  rectangle net +5V: 95.587,104.9 96.087,105.9
  rectangle net +5V: 94.637,104.25 95.737,107.15
  rectangle net +BATT: 96.087,110.2 98.187,111.4
  rectangle net +3V3: 135.187,70.9 135.887,72
  rectangle net MB: 135.928,114.397 136.822,119.373
  rectangle net GND: 122.087,103.2 122.687,103.5
  rectangle net VBUS1: 199.687,139.3 200.287,140.5
  rectangle net VBUS1: 194.887,139.3 195.487,140.5
  rectangle net DP2: 197.187,61.5 197.387,62.3
  rectangle net VBUS2: 199.687,60.5 200.287,62.3
  rectangle net VBUS2: 194.887,60.3 195.487,62.1
  rectangle net GND: 160.087,116.7 160.487,117.7
  rectangle net MB: 167.537,132.45 179.037,136.75
  rectangle net MB: 130.887,119.1 152.387,135.7
  rectangle net GND: 98.987,109.2 104.287,110.6
  rectangle net +BATT: 97.787,110.8 101.287,111.5
  rectangle net +BATT: 96.487,111.3 101.287,113
  rectangle net +SMPS: 96.087,113.6 98.087,117
  rectangle net -MOTOR: 86.787,137.2 90.587,139.6
  rectangle net +MOTOR: 119.487,111.35 124.787,114.85
  rectangle net -MOTOR: 126.787,111.35 132.987,114.85
  rectangle net MB: 130.787,135.3 179.537,144.2
  rectangle net MA: 110.887,119.1 130.387,144.3
  rectangle net -MOTOR: 126.787,114.1 132.987,118.6
  rectangle net -MOTOR: 111.787,115.3 126.987,118.6
  rectangle net -MOTOR: 111.887,114.7 112.687,115.7
  rectangle net GND: 120.887,68.8 124.137,72.25
  rectangle net GND: 121.587,71.95 123.387,76.6
  region net +MOTOR: 140.197,113.116 140.703,113.116 142.087,114.5 143.187,115.6 143.187,117.3 140.287,117.3 139.787,116.8 139.787,113.526 140.197,113.116
Bottom Layer:
  region: 103.287,38.6 103.287,39.6 104.287,39.6 104.287,38.6
  region: 191.387,78.9 191.387,77.9 190.387,77.9 190.387,78.9
  region: 196.987,104.7 197.987,104.7 197.987,103.7 196.987,103.7
  region: 191.387,123.9 191.387,122.9 190.387,122.9 190.387,123.9
  rectangle net A1/CH_B: 163.987,59.2 164.687,59.5
  rectangle net -MOTOR: 65.387,128 74.087,132.1
  rectangle net -MOTOR: 63.487,131.6 75.987,135
  rectangle net +MOTOR: 74.687,140.4 106.087,141.6
  rectangle net +MOTOR: 66.187,138 76.087,141.2
  rectangle net VBUS1: 195.487,117.1 199.387,119.6
  rectangle net VBUS2: 195.587,64.4 199.487,66.9
  rectangle net +MOTOR: 136.187,111.1 143.187,116.3
  rectangle net +MOTOR: 113.24,133.02 117.565,143.067
  rectangle net +MOTOR: 105.17,138.132 117.584,143.713
  rectangle net +MOTOR: 117.496,116.213 143.225,134.98
  rectangle net MA: 186.087,131.15 189.188,135.34
  rectangle net +MOTOR: 53.587,126.1 61.887,130.3
  rectangle net +MOTOR: 53.587,130.1 56.787,140
  rectangle net MA: 117.891,135.157 189.187,144.2

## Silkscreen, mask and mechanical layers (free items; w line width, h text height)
Top Overlay:
  lines w0.15 net S$18375: 53.287,56.897 189.287,56.9 ; 53.287,144.9 189.387,144.9
  text "QtOpenGuidance" at 120.287,130.784 h2.03
  text "CANtact" at 105.587,87.584 h2.03
  text "o" at 93.734,77.06 h1 r136
Top Solder:
  region: 103.287,38.6 103.287,39.6 104.287,39.6 104.287,38.6
  region: 191.387,78.9 191.387,77.9 190.387,77.9 190.387,78.9
  region: 196.987,104.7 197.987,104.7 197.987,103.7 196.987,103.7
  region: 191.387,123.9 191.387,122.9 190.387,122.9 190.387,123.9
  text "12-2020" at 122.687,123.4 h2.03
Bottom Solder:
  region: 103.287,38.6 103.287,39.6 104.287,39.6 104.287,38.6
  region: 191.387,78.9 191.387,77.9 190.387,77.9 190.387,78.9
  region: 196.987,104.7 197.987,104.7 197.987,103.7 196.987,103.7
  region: 191.387,123.9 191.387,122.9 190.387,122.9 190.387,123.9
Document:
  lines w0.003: 125.468,93.328 125.519,93.379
